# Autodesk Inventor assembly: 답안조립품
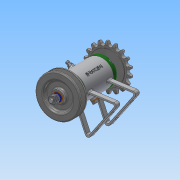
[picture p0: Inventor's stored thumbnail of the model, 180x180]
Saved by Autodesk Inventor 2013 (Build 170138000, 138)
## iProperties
Created: 2016-03
Part Number: 답안조립품
Document SubType Name: Assembly
Designer: Administrator
Author: Administrator
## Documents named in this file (16)
- C:\Users\Administrator\Desktop\460308V1022\답안조립품.iam
- C:\Users\Administrator\Desktop\460308V1022\1.본체.ipt
- C:\Users\Administrator\Desktop\460308V1022\V벨트풀리.ipt
- C:\Users\Administrator\Desktop\460308V1022\너트 M 8.ipt
- C:\Users\Administrator\Desktop\460308V1022\니플 M 6 x 0.75.ipt
- C:\Users\Administrator\Desktop\460308V1022\베어링 15 x 32 x 9.ipt
- C:\Users\Administrator\Desktop\460308V1022\볼트 M 6 x 8.ipt
- C:\Users\Administrator\Desktop\460308V1022\볼트 M4 x 12.ipt
- C:\Users\Administrator\Desktop\460308V1022\스프로킷.ipt
- C:\Users\Administrator\Desktop\460308V1022\스프링와셔 8.ipt
- C:\Users\Administrator\Desktop\460308V1022\오일 실 15 25 7.ipt
- C:\Users\Administrator\Desktop\460308V1022\와셔 6x11.5.ipt
- C:\Users\Administrator\Desktop\460308V1022\와셔 8x17.ipt
- C:\Users\Administrator\Desktop\460308V1022\축.ipt
- C:\Users\Administrator\Desktop\460308V1022\커버.ipt
- C:\Users\Administrator\Desktop\460308V1022\키 3 x 3 x 12.ipt
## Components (12 placed, 4 different names)
1. 1.본체:1
2. KS B 2023 6002 - 15 x 32 x 9:1
3. V벨트풀리:1
4. KS B 2023 6002 - 15 x 32 x 9:2
5. ISO 4762 M4 x 12:1
6. ISO 4762 M4 x 12:3
7. ISO 4762 M4 x 12:4
8. ISO 4762 M4 x 12:5
9. ISO 4762 M4 x 12:2
10. ISO 4762 M4 x 12:6
11. ISO 4762 M4 x 12:7
12. ISO 4762 M4 x 12:8
